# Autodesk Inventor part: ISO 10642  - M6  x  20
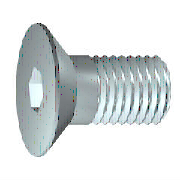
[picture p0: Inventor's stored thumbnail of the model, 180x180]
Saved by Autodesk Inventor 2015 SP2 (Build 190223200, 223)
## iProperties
IsCustomPart: 0
Created: 2012-02
Part Number: ISO 10642  - M6  x  20
Material: Stahl
Description: Innensechskantschraube mit Senkkopf
Document SubType Name: Modeling
Standard: ISO 10642
Designer: rYan
Standard Revision: 1998
Standards Organization: DIN
Language: de-DE
Size Designation: M6  x  20
Categories: <MemberInstance><Categories><Category DisplayName="Verbindungselemente" InternalName="e4da775c-781d-43d5-af7c-5136215cf5a6" Mnemonic="FSTN"><Category DisplayNam
Density: 7.85 g/cm^3
Mass: 5.4003 g
Surface Area: 6.03389 cm^2
Volume: 0.687936 cm^3
Appearance: Platte
Author: rYan
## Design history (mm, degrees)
body "Solid1"
revolve "Körper" stored, may be unused: angle "d13" = 90 deg
sketch "Skizze2"
  geometry: L1 (0, -7.938)-(0, 7.938) reference; L2 (-7.938, 0)-(7.938, 0) reference; L3 (2.309, 0)-(1.155, -2); L4 (1.155, -2)-(-1.155, -2); L5 (-1.155, -2)-(-2.309, 0); L6 (-2.309, 0)-(-1.155, 2); L7 (-1.155, 2)-(1.155, 2); L8 (1.155, 2)-(2.309, 0); A1 r 2.309 centre (0, 0) between (0, 2.309) and (2.309, 0) reference; 2 further points
  constraints: 12 end point, 2 coincident, 2 point on circle, 2 point on line, 12 other
extrude "Loch" join sketch "Skizze2" taper "d14" = 0 deg; stored distance "d30" = 10
feature "Gewinde" dims "d15" = 13.67 (= GEL), "d16" = 0
chamfer "Fase1" distance "d17" = 0.61345 (= -0.5 x SPD + 0.5 x GD); stored, may be unused: second distance "d18" = 0.61345 (= GUL), angle "d39" = 45 deg
workplane "Work Plane1"
sketch "Skizze1"
  geometry: L1 (20, 0)-(20, 3); L2 (20, 3)-(6.33, 3); L3 (6.33, 3)-(5.717, 3); L4 (0, 5.67)-(0, 2.309); L5 (0, 2.309)-(2.2, 2.309); L6 (2.2, 2.309)-(3.533, 0); L7 (3.533, 0)-(20, 0); L8 (0, 5.67)-(1.05, 5.67); L9 (1.05, 5.67)-(3.72, 3); L10 (5.717, 3)-(3.72, 3); L11 (6.33, 3)-(3.72, 3); L12 (3.72, 3)-(3.72, 3); L13 (-4, 0)-(24, 0) reference; L14 (0, -1.134)-(0, 6.804) reference
  constraints: 24 end point, 4 collinear, 3 parallel
  dimensions: "d0" = 20 distance between parallel lines of L4 L1 (= NLG); "d1" = 13.67 distance from line of L2.end L1 (= GEL); "d2" = 2.2 distance from line of L5.end L4 (= INTI); "d3" = 6 diameter of L2 L7 (= GD); "d6" = 3.72 distance from line of L9.end L4 (= KOH); "d7" = 45 deg angle of L9 L7 (= 0.5 x SEWI); "d8" = 4.6188 diameter of L5 L7 (= 1.1547 x SW); "d9" = 60 deg angle of L6 L7; "d10" = 11.34 diameter of L8 L7 (= KOD); "d11" = 6 diameter of L10 L7 (= BDM); "d12" = 0.61345 distance of L3.end L2.end (= GAL)
other parameters: "NLG" = 20 [user parameter; used in 1 equation term], "INTI" = 2.2 [user parameter; used in 1 equation term], "GEL" = 13.67 [user parameter; used in 2 equation terms], "GAL" = 0.61345 (= 0.61345 x PTC) [user parameter; used in 1 equation term], "KOH" = 3.72 [user parameter; used in 1 equation term], "KOD" = 11.34 [user parameter; used in 1 equation term], "GUL" = 0.61345 (= 0.61345 x PTC) [user parameter; used in 1 equation term], "SPD" = 4.7731 (= NND - 1.2269 x PTC) [user parameter; used in 1 equation term], "BDM" = 6 (= NND) [user parameter; used in 1 equation term], "GD" = 6 (= NND) [user parameter; used in 2 equation terms], "SEWI" = 90 deg [user parameter; used in 1 equation term], "d20" = 0, "SW" = 4 [user parameter; used in 1 equation term], "d43" = 0, "d44" = 0, "TOA" = 30 deg [user parameter], "GD1" = 4.7731 (= THREADDIA - 1.2269 x PTC) [user parameter], "EPV" = 6.72 [user parameter], "THREADDIA" = 6 [user parameter; used in 1 equation term], "PTC" = 1 [user parameter; used in 5 equation terms], "NND" = 6 [user parameter; used in 3 equation terms], "E0" = 4.62 [user parameter]
